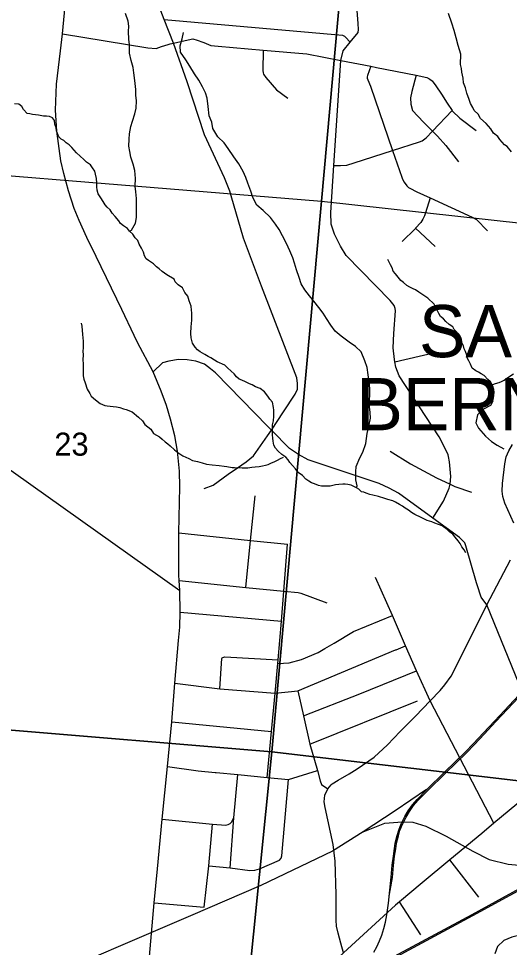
# Model space of a CAD drawing. Extents: x -8.2 to 38.5, y -0.1 to 21.9.
# Drawn here: x 6.498 to 7.39, y 18.635 to 20.321 of the extents above; entities that cross this region are included whole.
import ezdxf

# ---------------------------------------------------------------- set-up
doc = ezdxf.new("R2010")
doc.units = 0
for name, color, linetype in [('Default', 7, 'Continuous'), ('GM_X_Adjacent_County_Text', 7, 'Continuous'), ('GM_X_County_Road_Text', 7, 'Continuous'), ('GM_X_County_Subdivision', 7, 'Continuous'), ('GM_X_Minor_River', 7, 'Continuous'), ('GM_X_Township_Subdivision_Text', 7, 'Continuous'), ('GM_X_Township_Text', 7, 'Continuous'), ('GM_X_US_Location', 7, 'Continuous')]:
    doc.layers.add(name, color=color, linetype=linetype)

msp = doc.modelspace()

# ---------------------------------------------------------------- linework, layer by layer
at = {"layer": 'Default'}
for points in [[(7.1182, 20.7645), (6.1116, 20.7645), (6.0401, 20.072), (7.0485, 19.9899)], [(8.1752, 20.7645), (7.1182, 20.7645), (7.0485, 19.9899), (8.0944, 19.8749)]]:
    msp.add_lwpolyline(points, close=True, dxfattribs=at)
at = {"layer": 'GM_X_Adjacent_County_Text'}
for points in [[(7.0485, 19.9899), (6.9585, 18.9896), (5.9396, 19.0747), (6.0401, 20.072)], [(7.0485, 19.9899), (8.0944, 19.8749), (7.9789, 18.8702), (6.9585, 18.9896)], [(5.9396, 19.0747), (6.9585, 18.9896), (6.8589, 17.9964), (5.838, 18.0925)], [(6.9585, 18.9896), (7.9789, 18.8702), (7.8777, 17.8803), (6.8589, 17.9964)]]:
    msp.add_lwpolyline(points, close=True, dxfattribs=at)
at = {"layer": 'GM_X_Minor_River'}
for points in [[(6.7001, 19.9352), (6.7035, 19.9371), (6.711, 19.9499), (6.7128, 19.9601), (6.7127, 19.9723), (6.7126, 19.9825), (6.7125, 19.9947), (6.7117, 20.0069), (6.7104, 20.0172), (6.7107, 20.0312), (6.7099, 20.0453), (6.7068, 20.0572), (6.7025, 20.0698), (6.7005, 20.0798), (6.6988, 20.0897), (6.6991, 20.1022), (6.7001, 20.1121), (6.7023, 20.1253), (6.7056, 20.1351), (6.7094, 20.1487), (6.7119, 20.1586), (6.7126, 20.1719), (6.7117, 20.1825), (6.7112, 20.1924), (6.7097, 20.2092), (6.7077, 20.2229), (6.7064, 20.2324), (6.7029, 20.2451), (6.7002, 20.2588), (6.6998, 20.274), (6.6986, 20.2843), (6.6981, 20.298), (6.6987, 20.3075), (6.6978, 20.317), (6.6928, 20.3309)], [(7.3013, 20.2379), (7.3021, 20.2567), (7.2968, 20.2728), (7.2937, 20.2865), (7.2898, 20.2999), (7.2856, 20.3133), (7.2792, 20.331)], [(7.1121, 19.4694), (7.1138, 19.4732), (7.111, 19.4839), (7.111, 19.4984), (7.112, 19.5082), (7.1184, 19.5237), (7.124, 19.5342), (7.1293, 19.5496), (7.1316, 19.5678), (7.135, 19.5811), (7.1376, 19.5958), (7.1371, 19.6061), (7.1362, 19.6164), (7.1361, 19.6282), (7.1364, 19.6381), (7.1366, 19.6491), (7.1351, 19.6628), (7.1334, 19.6746), (7.1315, 19.6876), (7.1276, 19.7002), (7.1208, 19.7164), (7.1107, 19.7257), (7.0991, 19.7336), (7.0846, 19.745), (7.0738, 19.754), (7.0657, 19.7645), (7.058, 19.7768), (7.0518, 19.7865), (7.044, 19.7966), (7.0348, 19.8082), (7.0271, 19.8179), (7.0186, 19.8287), (7.012, 19.8395), (7.0081, 19.851), (7.0035, 19.8652), (6.9996, 19.8771), (6.9964, 19.8867), (6.991, 19.8997), (6.9853, 19.9132), (6.978, 19.927), (6.9718, 19.9382), (6.9652, 19.9479), (6.956, 19.9603), (6.9426, 19.9728), (6.9311, 19.9829), (6.9242, 19.9968), (6.9203, 20.0083), (6.915, 20.0228), (6.9114, 20.0328), (6.9067, 20.044), (6.8983, 20.0578), (6.8895, 20.0706), (6.8792, 20.0853), (6.8719, 20.0961), (6.8604, 20.1067), (6.8512, 20.1221), (6.8496, 20.1332), (6.8449, 20.1451), (6.8427, 20.1618), (6.8408, 20.1771), (6.838, 20.1867), (6.8325, 20.1978), (6.826, 20.2094), (6.8183, 20.2214), (6.8095, 20.2352), (6.8022, 20.2465), (6.7926, 20.2604), (6.7921, 20.2722), (6.7955, 20.2846), (6.798, 20.296)], [(7.3941, 20.0796), (7.3863, 20.089), (7.3815, 20.0922), (7.3726, 20.1019), (7.369, 20.1074), (7.3615, 20.1133), (7.3564, 20.1214), (7.3479, 20.1312), (7.3379, 20.1402), (7.3335, 20.1479), (7.3261, 20.1546), (7.324, 20.16), (7.3192, 20.167), (7.3171, 20.1746), (7.3129, 20.1858), (7.3105, 20.1958), (7.3069, 20.205), (7.306, 20.2134), (7.304, 20.2241), (7.3031, 20.231), (7.3013, 20.2379)], [(6.8732, 19.6922), (6.8594, 19.6983), (6.8542, 19.7012), (6.8478, 19.7055), (6.8429, 19.7076), (6.8366, 19.7115), (6.8283, 19.7163), (6.8235, 19.7199), (6.8195, 19.725), (6.8143, 19.7323), (6.8123, 19.7419), (6.8117, 19.7495), (6.8121, 19.7621), (6.8126, 19.7674), (6.8132, 19.7742), (6.8133, 19.7803), (6.8131, 19.7868), (6.8125, 19.7918), (6.8119, 19.7994), (6.8084, 19.809), (6.806, 19.8171), (6.8008, 19.8241), (6.7961, 19.8322), (6.7886, 19.8381), (6.7827, 19.8432), (6.7809, 19.8482), (6.7675, 19.8562), (6.7592, 19.8621), (6.7541, 19.8672), (6.7488, 19.8704), (6.7437, 19.8763), (6.7347, 19.8822), (6.7302, 19.8854), (6.7273, 19.8904), (6.7252, 19.897), (6.7216, 19.9047), (6.7176, 19.9116), (6.7151, 19.9182), (6.7103, 19.9233), (6.7059, 19.9302), (6.7, 19.9354), (6.6963, 19.9404), (6.6892, 19.9448), (6.6836, 19.9495), (6.6807, 19.9542), (6.6737, 19.962), (6.6685, 19.9678), (6.6649, 19.974), (6.6593, 19.9787), (6.656, 19.9834), (6.652, 19.9892), (6.648, 19.9958), (6.6433, 20.0035), (6.6411, 20.0101), (6.6409, 20.0158), (6.6404, 20.0234), (6.6402, 20.031), (6.6381, 20.0391), (6.6367, 20.0441), (6.6327, 20.0507), (6.6291, 20.0557), (6.6216, 20.0605), (6.6168, 20.0656), (6.6101, 20.0718), (6.6038, 20.0777), (6.5997, 20.0828), (6.5953, 20.0871), (6.5901, 20.0922), (6.5849, 20.0961), (6.5804, 20.1001), (6.5759, 20.1025), (6.5715, 20.1068), (6.5694, 20.1129), (6.5676, 20.1179), (6.5666, 20.1233), (6.5645, 20.1295), (6.5635, 20.1363), (6.5599, 20.141), (6.5546, 20.1438), (6.5493, 20.1443), (6.5436, 20.1445), (6.5349, 20.1459), (6.5235, 20.147), (6.519, 20.1482), (6.5141, 20.1491), (6.5074, 20.1565), (6.5041, 20.162), (6.4989, 20.1663), (6.4913, 20.1665)], [(7.3602, 19.6269), (7.3612, 19.6326), (7.3617, 19.6375), (7.3622, 19.6428), (7.362, 19.6481), (7.3602, 19.6539), (7.3559, 19.6616), (7.351, 19.6663), (7.3444, 19.673), (7.3388, 19.6766), (7.3339, 19.6794), (7.3294, 19.6818), (7.3227, 19.6869), (7.3195, 19.6939), (7.3166, 19.6997), (7.3137, 19.7051), (7.3127, 19.71), (7.3106, 19.7166), (7.308, 19.722), (7.3067, 19.7273), (7.303, 19.7339), (7.3013, 19.7397), (7.2973, 19.7463), (7.2951, 19.7516), (7.29, 19.7571), (7.2871, 19.7618), (7.2807, 19.7661), (7.2744, 19.7713), (7.2703, 19.7759), (7.2651, 19.7806), (7.2622, 19.7857), (7.2582, 19.793), (7.2535, 19.8027), (7.2417, 19.8137), (7.2331, 19.82), (7.2256, 19.8248), (7.2196, 19.8287), (7.2151, 19.8308), (7.2095, 19.8336), (7.2039, 19.8368), (7.1976, 19.8419), (7.1927, 19.8459), (7.1879, 19.8517), (7.1832, 19.8579), (7.1791, 19.863), (7.177, 19.8687), (7.1741, 19.8742), (7.1716, 19.8792), (7.1694, 19.8838)], [(6.6122, 19.7684), (6.6132, 19.7631), (6.6147, 19.7478), (6.6155, 19.7356), (6.6156, 19.7227), (6.6154, 19.7181), (6.6156, 19.7101), (6.6154, 19.7021), (6.6155, 19.6941), (6.6157, 19.6869), (6.6159, 19.6785), (6.6161, 19.6724), (6.6171, 19.6667), (6.6192, 19.6597), (6.6231, 19.6486), (6.6278, 19.6405), (6.6303, 19.6355), (6.6385, 19.6291), (6.6467, 19.6224), (6.655, 19.6188), (6.6595, 19.6183), (6.6701, 19.6172), (6.6766, 19.6163), (6.6823, 19.615), (6.689, 19.6129), (6.6939, 19.6116), (6.7049, 19.6071), (6.7164, 19.5977), (6.7238, 19.591), (6.7278, 19.584), (6.7386, 19.5757), (6.7437, 19.568), (6.7546, 19.5616), (6.7594, 19.5576), (6.765, 19.5529), (6.7695, 19.549), (6.7739, 19.5458), (6.7817, 19.5383), (6.7877, 19.5336), (6.797, 19.5276), (6.8075, 19.5224), (6.8147, 19.5192), (6.8237, 19.517), (6.832, 19.5145), (6.84, 19.5124), (6.8502, 19.5109), (6.8627, 19.5098), (6.8718, 19.5088), (6.8771, 19.5079), (6.8862, 19.5065), (6.8908, 19.506), (6.9048, 19.5056), (6.9147, 19.5057), (6.922, 19.5066), (6.9284, 19.5072), (6.9353, 19.5082), (6.9418, 19.5091), (6.9472, 19.5105), (6.9518, 19.5119), (6.9579, 19.5148), (6.9629, 19.5165), (6.9691, 19.5198), (6.9741, 19.5223), (6.9795, 19.5252)], [(7.311, 19.3511), (7.3077, 19.3565), (7.3037, 19.362), (7.3008, 19.3682), (7.2971, 19.3732), (7.2916, 19.3798), (7.2876, 19.3853), (7.2816, 19.3893), (7.2772, 19.3936), (7.2682, 19.4003), (7.2546, 19.4049), (7.249, 19.4077), (7.2407, 19.4102), (7.2298, 19.4151), (7.2182, 19.4207), (7.2122, 19.4243), (7.207, 19.429), (7.201, 19.4322), (7.1958, 19.4362), (7.1905, 19.439), (7.1834, 19.4434), (7.1785, 19.4454), (7.1695, 19.448), (7.1638, 19.45), (7.1521, 19.4534), (7.1423, 19.456), (7.1366, 19.4573), (7.1302, 19.4597), (7.1257, 19.4614), (7.1212, 19.4623), (7.1167, 19.4666), (7.1122, 19.4694), (7.1025, 19.4742), (7.0968, 19.4755), (7.0919, 19.476), (7.0873, 19.4761), (7.0805, 19.4756), (7.074, 19.475), (7.0694, 19.4736), (7.0648, 19.4726), (7.0564, 19.4724), (7.0488, 19.4726), (7.0435, 19.4736), (7.036, 19.4764), (7.0304, 19.4785), (7.0255, 19.4813), (7.0203, 19.4849), (7.014, 19.4915), (7.0065, 19.4974), (7.0014, 19.504), (6.9962, 19.5099), (6.9914, 19.5154), (6.9881, 19.52), (6.9837, 19.5247), (6.977, 19.5299), (6.9699, 19.5361), (6.9651, 19.5416), (6.9622, 19.547), (6.9609, 19.5543), (6.9606, 19.5592), (6.96, 19.5653), (6.9595, 19.5722), (6.9598, 19.5836), (6.9615, 19.5908), (6.9621, 19.5996), (6.9624, 19.6102), (6.9618, 19.6152), (6.9597, 19.6247), (6.9549, 19.6302), (6.9513, 19.636), (6.945, 19.6438), (6.9372, 19.6497), (6.9286, 19.653), (6.9226, 19.6566), (6.918, 19.6579), (6.9105, 19.6615), (6.9042, 19.6647), (6.8993, 19.6668), (6.8944, 19.6707), (6.89, 19.6762), (6.8844, 19.6809), (6.8781, 19.6875), (6.8732, 19.6922)], [(7.3599, 19.657), (7.3649, 19.6587), (7.3714, 19.6608), (7.376, 19.6626), (7.3807, 19.6648), (7.3853, 19.6684), (7.3973, 19.6761)], [(7.3602, 19.6269), (7.3559, 19.619), (7.3428, 19.6121), (7.332, 19.6017), (7.3293, 19.5874), (7.3337, 19.5777), (7.3466, 19.5634), (7.3578, 19.5536), (7.3679, 19.5465), (7.3802, 19.5401)], [(7.5014, 18.6975), (7.4944, 18.6928), (7.4816, 18.6806), (7.4726, 18.6706), (7.4622, 18.6656), (7.4499, 18.6602), (7.4389, 18.6582), (7.4256, 18.6575), (7.4134, 18.6578), (7.3943, 18.653), (7.3801, 18.6469), (7.3688, 18.6362), (7.3635, 18.6231)]]:
    msp.add_lwpolyline(points, dxfattribs=at)
at = {"layer": 'GM_X_Township_Subdivision_Text'}
for p, q in [((7.2198, 19.9406), (7.255, 19.9076)), ((7.1822, 19.6979), (7.2524, 19.7147)), ((6.7923, 19.2433), (6.9759, 19.2272)), ((7.1843, 19.1753), (7.2015, 19.1825)), ((7.0276, 19.0036), (7.2231, 19.0822)), ((6.7767, 19.0441), (6.9578, 19.0268)), ((7.3347, 18.7261), (7.2819, 18.7934)), ((6.7448, 18.7159), (6.8357, 18.7079)), ((7.2294, 18.6576), (7.1902, 18.7173))]:
    msp.add_line(p, q, dxfattribs=at)
for points in [[(6.8354, 19.4678), (6.852, 19.4742), (6.8795, 19.4939), (6.8962, 19.5055), (6.9121, 19.5165), (6.9254, 19.5275), (6.9507, 19.5636), (6.9579, 19.5743), (6.98, 19.6074), (7.0012, 19.6392), (7.0049, 19.6486), (7.0052, 19.6585), (7.004, 19.6692), (6.9397, 19.8355), (6.9069, 19.9227), (6.8845, 19.9998), (6.8824, 20.0082), (6.8725, 20.0324), (6.836, 20.1106), (6.805, 20.2065), (6.7797, 20.2771), (6.7631, 20.32), (6.7447, 20.3674)], [(7.251, 19.4143), (7.2703, 19.4448), (7.2809, 19.4684), (7.2823, 19.4759), (7.2838, 19.4896), (7.2816, 19.5163), (7.2797, 19.5261), (7.2787, 19.529), (7.2764, 19.5346), (7.2624, 19.562), (7.19, 19.6728), (7.184, 19.6882), (7.1822, 19.6979), (7.1813, 19.7023), (7.1789, 19.7233), (7.1801, 19.7495), (7.1832, 19.7908), (7.1827, 19.795), (7.1808, 19.8003), (7.1738, 19.8097), (7.0934, 19.891), (7.0832, 19.9084), (7.0721, 19.93), (7.0665, 19.9484), (7.0656, 19.9694), (7.0712, 20.0547), (7.0836, 20.2455), (7.0879, 20.2627), (7.1009, 20.2788), (7.1151, 20.2965), (7.116, 20.3018), (7.1156, 20.3124), (7.1117, 20.3612)], [(6.7631, 20.32), (7.0872, 20.2916), (7.0896, 20.2903), (7.0905, 20.2895), (7.0924, 20.2877), (7.1009, 20.2788)], [(6.578, 20.2937), (6.7331, 20.2682), (6.7486, 20.2674), (6.7582, 20.2705), (6.7703, 20.2742)], [(6.7703, 20.2742), (6.7741, 20.2754), (6.7797, 20.2771), (6.8122, 20.2841), (6.8151, 20.2845), (6.8171, 20.2842), (6.8209, 20.2831), (6.8348, 20.2781), (6.848, 20.2724), (6.8609, 20.2713), (6.9428, 20.2643), (7.0224, 20.2574), (7.0836, 20.2455), (7.1381, 20.235), (7.1484, 20.2329)], [(6.9428, 20.2643), (6.942, 20.2271), (6.9427, 20.2231), (6.9437, 20.2206), (6.9477, 20.2144), (6.9672, 20.1922), (6.9877, 20.1772)], [(7.1381, 20.235), (7.1323, 20.2182), (7.132, 20.2158), (7.132, 20.2131), (7.1327, 20.2105), (7.1379, 20.1985), (7.1779, 20.0817), (7.1945, 20.0336), (7.1961, 20.0299), (7.1991, 20.0247), (7.2038, 20.0179), (7.2071, 20.0146), (7.209, 20.0134), (7.2218, 20.0069), (7.2461, 19.9958), (7.3227, 19.9607), (7.3306, 19.9566), (7.3505, 19.9363)], [(7.1484, 20.2329), (7.221, 20.2189), (7.2404, 20.2142), (7.2436, 20.2127), (7.2458, 20.2116), (7.2483, 20.2097), (7.2501, 20.2082), (7.2563, 20.1996), (7.2669, 20.1841), (7.2771, 20.1679), (7.2863, 20.1545), (7.2869, 20.1535), (7.2998, 20.1406), (7.3296, 20.1185)], [(7.221, 20.2189), (7.2127, 20.1888), (7.2105, 20.1778), (7.2109, 20.166), (7.2143, 20.1545), (7.2339, 20.1331), (7.2504, 20.117), (7.2597, 20.108), (7.2744, 20.0912), (7.2979, 20.0613)], [(7.0712, 20.0547), (7.0833, 20.0547), (7.0948, 20.0555), (7.1082, 20.0593), (7.1779, 20.0817), (7.2271, 20.0976), (7.2317, 20.0997), (7.2387, 20.1048), (7.2504, 20.117), (7.2863, 20.1545)], [(7.2461, 19.9958), (7.2378, 19.9685), (7.236, 19.9634), (7.2326, 19.9569), (7.2293, 19.9512), (7.2198, 19.9406), (7.2187, 19.9394), (7.1952, 19.9165)], [(7.1734, 19.5358), (7.2104, 19.513), (7.2579, 19.4873), (7.2823, 19.4759), (7.2909, 19.4719), (7.3214, 19.4615)], [(6.9115, 19.2881), (6.92, 19.3736), (6.9282, 19.4545)], [(6.7894, 19.3877), (6.92, 19.3736), (6.9872, 19.3668)], [(6.9499, 18.9434), (6.9578, 19.0268), (6.9645, 19.0961), (6.9696, 19.1503), (6.9701, 19.1568), (6.9759, 19.2272), (6.9802, 19.2814), (6.9872, 19.3668)], [(6.7904, 19.3009), (6.9115, 19.2881), (6.9802, 19.2814), (7.0062, 19.2789), (7.0112, 19.278), (7.0582, 19.2603)], [(7.3621, 18.8604), (7.2463, 19.0826), (7.2214, 19.1369), (7.2015, 19.1825), (7.1776, 19.2373), (7.1469, 19.3067)], [(6.9696, 19.1503), (6.99, 19.1514), (7.0125, 19.1574), (7.0428, 19.1705), (7.0551, 19.1774), (7.0635, 19.1824), (7.0719, 19.1873), (7.1069, 19.2083), (7.1776, 19.2373)], [(6.7821, 19.1146), (6.8638, 19.1043), (6.9645, 19.0961), (7.0059, 19.1007), (7.1834, 19.1749), (7.1843, 19.1753)], [(6.8638, 19.1043), (6.868, 19.1595), (6.8685, 19.1604), (6.8695, 19.1614), (6.8712, 19.162), (6.8734, 19.1621), (6.9701, 19.1568)], [(7.0161, 19.0552), (7.1187, 19.0949), (7.2214, 19.1369)], [(7.0059, 19.1007), (7.0161, 19.0552), (7.0276, 19.0036), (7.0414, 18.9561), (7.0461, 18.9371), (7.0486, 18.9306), (7.0604, 18.9226)], [(6.7692, 18.9632), (6.8249, 18.9552), (6.8557, 18.9523), (6.8576, 18.9521)], [(6.8576, 18.9521), (6.8968, 18.9484), (6.9499, 18.9434), (6.989, 18.9397), (7.0414, 18.9561)], [(6.8829, 18.7791), (6.8896, 18.8698), (6.8968, 18.9484)], [(6.8443, 18.783), (6.8829, 18.7791), (6.9188, 18.7745), (6.9276, 18.775), (6.9364, 18.7774), (6.9722, 18.7931), (6.9757, 18.7968), (6.9766, 18.8009), (6.989, 18.9397)], [(6.7591, 18.8675), (6.851, 18.8586), (6.8749, 18.8568), (6.879, 18.8578), (6.8827, 18.8596), (6.885, 18.8619), (6.8896, 18.8698)], [(6.8357, 18.7079), (6.8443, 18.783), (6.851, 18.8586)]]:
    msp.add_lwpolyline(points, dxfattribs=at)
at = {"layer": 'GM_X_Township_Text'}
msp.add_line((7.0604, 18.9226), (7.0665, 18.9297), dxfattribs=at)
for points in [[(6.7147, 19.7335), (6.7082, 19.7459), (6.6861, 19.7933), (6.6396, 19.8893), (6.6223, 19.9239), (6.6086, 19.955), (6.5997, 19.9767), (6.5891, 20.0088), (6.5807, 20.0402), (6.575, 20.0631), (6.5678, 20.1173), (6.5658, 20.1551), (6.5674, 20.2022), (6.5749, 20.2632), (6.578, 20.2937), (6.5914, 20.4341), (6.6057, 20.5698), (6.6177, 20.6816), (6.6222, 20.7111), (6.6291, 20.7348), (6.6413, 20.7645)], [(6.3023, 20.2084), (6.3014, 20.1975), (6.302, 20.1747), (6.3036, 20.1519), (6.305, 20.134), (6.3189, 20.0826), (6.349, 19.9824), (6.3625, 19.9326), (6.376, 19.8759), (6.3826, 19.8222), (6.3906, 19.7489), (6.3945, 19.7196), (6.3995, 19.6922), (6.4258, 19.5921), (6.4312, 19.5594), (6.436, 19.5464), (6.4427, 19.5346), (6.4528, 19.5227), (6.489, 19.4976), (6.7912, 19.2826)], [(6.7898, 19.3108), (6.7894, 19.3196), (6.7894, 19.3877), (6.79, 19.4155), (6.7913, 19.471), (6.7907, 19.4993), (6.7871, 19.536), (6.7823, 19.5636), (6.7746, 19.594), (6.7672, 19.6188), (6.7575, 19.6448), (6.7427, 19.6802), (6.7147, 19.7335)], [(6.9579, 19.5743), (6.9515, 19.5808), (6.8561, 19.6782), (6.8471, 19.6855), (6.8362, 19.694), (6.8203, 19.6995), (6.8048, 19.7016), (6.7889, 19.7021), (6.7714, 19.6996), (6.76, 19.6963), (6.7427, 19.6802)], [(7.3317, 19.293), (7.3303, 19.2969), (7.3108, 19.3639), (7.309, 19.3693), (7.2996, 19.3789), (7.251, 19.4143), (7.1885, 19.4598), (7.1719, 19.4687), (7.1534, 19.4769), (7.0245, 19.5204), (7.0068, 19.5301), (6.9909, 19.5405), (6.9579, 19.5743)], [(7.3983, 19.4051), (7.3816, 19.4413), (7.3783, 19.4533), (7.3769, 19.4631), (7.3774, 19.4774), (7.3821, 19.5128), (7.3844, 19.5256), (7.3893, 19.5366), (7.3959, 19.5481)], [(7.0665, 18.9297), (7.0683, 18.9318), (7.0793, 18.9386), (7.0991, 18.9496), (7.1138, 18.9588), (7.1442, 18.9803), (7.1684, 19.0023), (7.1915, 19.0266), (7.2193, 19.0547), (7.2463, 19.0826), (7.2643, 19.1013), (7.2731, 19.1116), (7.2846, 19.1275), (7.2921, 19.1423), (7.3494, 19.2569), (7.3921, 19.3388)], [(6.7285, 18.5276), (6.7448, 18.7159), (6.7506, 18.7771), (6.7591, 18.8675), (6.7692, 18.9632), (6.7767, 19.0441), (6.7821, 19.1146), (6.7892, 19.1919), (6.7915, 19.2162), (6.7923, 19.2433), (6.7912, 19.2826), (6.7904, 19.3009), (6.7898, 19.3108)], [(7.4733, 18.9524), (7.3494, 19.2569), (7.3387, 19.2705), (7.3317, 19.293)], [(7.5229, 18.9817), (7.5089, 18.9754), (7.4899, 18.9643), (7.4733, 18.9524), (7.3621, 18.8604), (7.3401, 18.8418), (7.2819, 18.7934), (7.2316, 18.752), (7.1902, 18.7173), (7.1834, 18.7111)], [(7.0887, 18.6247), (7.0839, 18.6426), (7.0788, 18.6603), (7.0763, 18.6735), (7.0754, 18.6841), (7.0756, 18.7308), (7.0739, 18.7915), (7.0701, 18.8215), (7.0555, 18.889), (7.0538, 18.8993), (7.0551, 18.9113), (7.0604, 18.9226)], [(7.1834, 18.7111), (7.0958, 18.6314), (7.0887, 18.6247), (7.0391, 18.5787), (6.9965, 18.5424), (6.9718, 18.5255), (6.9503, 18.5121), (6.9359, 18.5062), (6.9229, 18.5033), (6.9158, 18.5026), (6.9029, 18.5029), (6.8189, 18.5151), (6.7285, 18.5276)]]:
    msp.add_lwpolyline(points, dxfattribs=at)
at = {"layer": 'GM_X_US_Location'}
for points in [[(7.1439, 18.626), (7.1493, 18.6358), (7.1544, 18.6468), (7.1583, 18.657), (7.1621, 18.6692), (7.165, 18.6802), (7.1672, 18.694), (7.1702, 18.7148), (7.1753, 18.762), (7.1773, 18.7838), (7.1793, 18.8006), (7.1811, 18.8143), (7.1826, 18.8242), (7.186, 18.8377), (7.189, 18.8476), (7.1938, 18.8593), (7.2002, 18.8724), (7.2065, 18.8829), (7.2142, 18.8938), (7.2224, 18.9035), (7.2396, 18.9211), (7.2731, 18.9537), (7.3095, 18.9894), (7.3248, 19.0051), (7.3426, 19.0238), (7.3639, 19.0464), (7.4159, 19.1016)], [(7.1716, 18.7279), (7.1777, 18.7618), (7.1797, 18.7835), (7.1817, 18.8003), (7.1836, 18.8139), (7.1851, 18.8237), (7.1884, 18.837), (7.1913, 18.8468), (7.1961, 18.8582), (7.2024, 18.8712), (7.2086, 18.8815), (7.2162, 18.8922), (7.2242, 18.9018), (7.2414, 18.9193), (7.2748, 18.9519), (7.3113, 18.9876), (7.3266, 19.0034), (7.3444, 19.0221), (7.3657, 19.0447), (7.4177, 19.0999)], [(7.2394, 18.9216), (7.1829, 18.8829), (7.1243, 18.8448)], [(7.1243, 18.8448), (7.1638, 18.8603), (7.1951, 18.863)], [(7.1951, 18.863), (7.2149, 18.862), (7.2385, 18.8547), (7.275, 18.8366), (7.3235, 18.8092), (7.3535, 18.7944), (7.3881, 18.7857), (7.4211, 18.7826), (7.4645, 18.7864), (7.5115, 18.793)], [(7.1243, 18.8448), (7.0688, 18.8096), (6.9384, 18.7469), (6.8107, 18.6918), (6.2229, 18.4404)], [(7.5779, 18.8355), (7.5559, 18.8234), (7.5082, 18.7975), (7.4507, 18.7645), (7.3218, 18.6941), (7.1223, 18.5864), (7.0382, 18.5403)], [(7.5791, 18.8333), (7.5571, 18.8213), (7.5095, 18.7953), (7.4519, 18.7623), (7.323, 18.6919), (7.1235, 18.5842), (7.0457, 18.5415)]]:
    msp.add_lwpolyline(points, dxfattribs=at)

# ---------------------------------------------------------------- texts
at = {"layer": 'GM_X_County_Road_Text'}
msp.add_text('23', height=0.04186, rotation=0, dxfattribs=at).set_placement((6.5634, 19.5277))
at = {"layer": 'GM_X_County_Subdivision'}
for s, p in [('SAINT', (7.2259, 19.7065)), ('BERNARD', (7.1121, 19.5739))]:
    msp.add_text(s, height=0.0947, rotation=0, dxfattribs=at).set_placement(p)

doc.saveas('drawing.dxf')
